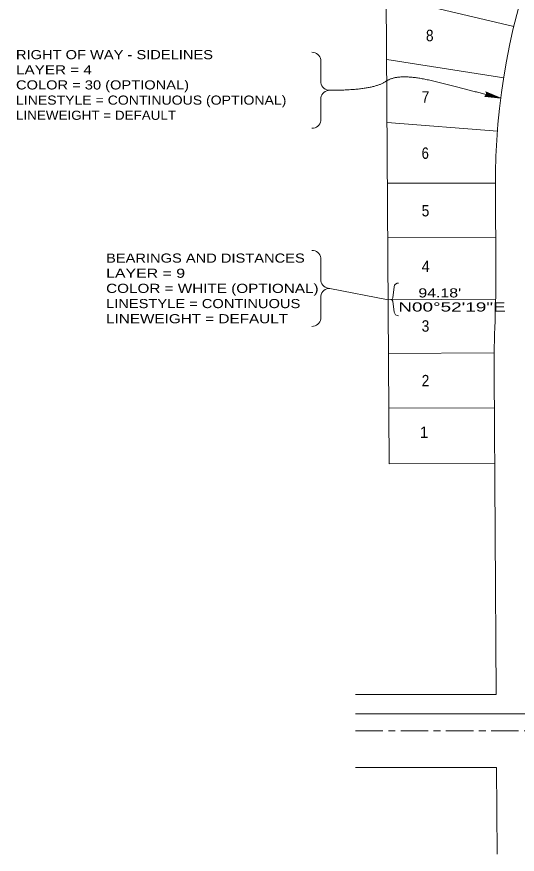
# Model space of a CAD drawing. Extents: x 6387474 to 6390971, y 1972046 to 1973920.
# Drawn here: x 6388753 to 6389192, y 1972046 to 1972779 of the extents above; entities that cross this region are included whole.
import ezdxf

# ---------------------------------------------------------------- set-up
doc = ezdxf.new("R2010")
doc.units = 0
doc.header["$LTSCALE"] = 4
doc.linetypes.add('LONG_DASH_SHORT_DASH', pattern=[9.9, 6, -1.2, 1.5, -1.2])
for name, color, linetype, lineweight in [('1', 7, 'Continuous', 13), ('2', 7, 'LONG_DASH_SHORT_DASH', 13), ('3', 7, 'Continuous', 13), ('4', 7, 'Continuous', 13), ('8', 7, 'Continuous', 13)]:
    doc.layers.add(name, color=color, linetype=linetype, lineweight=lineweight)
doc.layers.add('7', color=7, linetype='Continuous')

msp = doc.modelspace()

# ---------------------------------------------------------------- hatches: boundary and pattern name
at = {"layer": '8'}
for points in [[(6389177.432, 1972708.174), (6389163.863, 1972709.868), (6389163.361, 1972709.582)], [(6389177.432, 1972708.174), (6389164.286, 1972710.262), (6389163.863, 1972709.868)], [(6389177.432, 1972708.174), (6389164.608, 1972710.743), (6389164.286, 1972710.262)], [(6389164.318, 1972713.466), (6389164.629, 1972712.979), (6389177.432, 1972708.174)], [(6389164.81, 1972711.285), (6389164.608, 1972710.743), (6389177.432, 1972708.174)], [(6389164.629, 1972712.979), (6389164.821, 1972712.433), (6389177.432, 1972708.174)], [(6389164.882, 1972711.858), (6389164.81, 1972711.285), (6389177.432, 1972708.174)], [(6389164.821, 1972712.433), (6389164.882, 1972711.858), (6389177.432, 1972708.174)]]:
    msp.add_hatch(color=256, dxfattribs=at).paths.add_polyline_path(points)

# ---------------------------------------------------------------- linework, layer by layer
at = {"layer": '1'}
for p, q in [((6389072.576, 1973552.734), (6389079.624, 1972387.996)), ((6389079.624, 1972387.996), (6389172.122, 1972388.555))]:
    msp.add_line(p, q, dxfattribs=at)
at = {"layer": '2'}
msp.add_line((6389050.214, 1972153.984), (6389903.778, 1972153.984), dxfattribs=at)
at = {"layer": '3'}
for p, q in [((6389188.792, 1972770.788), (6389077.147, 1972797.257)), ((6389077.482, 1972741.929), (6389180.01, 1972725.798)), ((6389077.817, 1972686.64), (6389174.496, 1972679.126)), ((6389078.136, 1972633.771), (6389172.66, 1972633.627)), ((6389078.427, 1972585.832), (6389172.925, 1972586.404)), ((6389078.755, 1972531.513), (6389172.935, 1972532.083)), ((6389079.039, 1972484.534), (6389171.692, 1972485.095)), ((6389079.33, 1972436.475), (6389171.829, 1972437.035))]:
    msp.add_line(p, q, dxfattribs=at)
at = {"layer": '4'}
for p, q in [((6389172.666, 1972629.096), (6389173.104, 1972556.835)), ((6389171.645, 1972467.304), (6389173.348, 1972185.984)), ((6389050.214, 1972185.984), (6389173.348, 1972185.984)), ((6389050.213, 1972121.983), (6389173.735, 1972121.983)), ((6389173.735, 1972121.983), (6389174.195, 1972045.989))]:
    msp.add_line(p, q, dxfattribs=at)
for centre, radius, start, end in [((6389771.661, 1972632.72), 599, 137.65605, 180.34667), ((6388172.119, 1972551.261), 1001, 357.80051, 0.34648), ((6390196.627, 1972473.506), 1025, 177.8005, 180.34667)]:
    msp.add_arc(centre, radius, start, end, dxfattribs=at)
at = {"layer": '8'}
for p, q in [((6389019.82, 1972741.604), (6389019.82, 1972721.624)), ((6389019.82, 1972688.316), (6389019.82, 1972708.296)), ((6389019.82, 1972568.135), (6389019.82, 1972548.155)), ((6389078.755, 1972531.514), (6389027.708, 1972541.494)), ((6389084.019, 1972542.899), (6389082.813, 1972533.079)), ((6389019.82, 1972514.847), (6389019.82, 1972534.827)), ((6389082.812, 1972530.177), (6389084.022, 1972520.765)), ((6389050.214, 1972169.009), (6389919.45, 1972169.009))]:
    msp.add_line(p, q, dxfattribs=at)
for points in [[(6389075.095, 1972721.694), (6389075.585, 1972721.974), (6389076.055, 1972722.264), (6389076.507, 1972722.544), (6389076.94, 1972722.844), (6389077.371, 1972723.134), (6389077.816, 1972723.414), (6389078.276, 1972723.684), (6389078.75, 1972723.944), (6389079.239, 1972724.184), (6389079.743, 1972724.424), (6389080.262, 1972724.644), (6389080.795, 1972724.854), (6389081.342, 1972725.064), (6389081.905, 1972725.244), (6389082.482, 1972725.424), (6389083.073, 1972725.594), (6389083.679, 1972725.744), (6389084.3, 1972725.894), (6389084.936, 1972726.024), (6389085.586, 1972726.144), (6389086.251, 1972726.254), (6389086.93, 1972726.354), (6389087.624, 1972726.444), (6389088.333, 1972726.514), (6389089.056, 1972726.584), (6389089.794, 1972726.634), (6389090.547, 1972726.674), (6389091.314, 1972726.704), (6389092.096, 1972726.724), (6389092.893, 1972726.734), (6389093.704, 1972726.724), (6389094.53, 1972726.714), (6389095.371, 1972726.684), (6389096.226, 1972726.644), (6389097.095, 1972726.594), (6389097.98, 1972726.534), (6389098.879, 1972726.464), (6389099.793, 1972726.374), (6389100.721, 1972726.284), (6389101.664, 1972726.174), (6389102.622, 1972726.054), (6389103.594, 1972725.924), (6389104.581, 1972725.784), (6389105.582, 1972725.634), (6389106.598, 1972725.474), (6389107.629, 1972725.294), (6389108.675, 1972725.104), (6389109.735, 1972724.914), (6389110.81, 1972724.704), (6389111.899, 1972724.484), (6389113.003, 1972724.254)], [(6389113.003, 1972724.254), (6389114.122, 1972724.004), (6389115.255, 1972723.754), (6389116.403, 1972723.484), (6389117.566, 1972723.204), (6389118.743, 1972722.914), (6389119.935, 1972722.614), (6389121.132, 1972722.314), (6389122.324, 1972722.014), (6389123.513, 1972721.704), (6389124.697, 1972721.404), (6389125.877, 1972721.104), (6389127.052, 1972720.804), (6389128.223, 1972720.504), (6389129.39, 1972720.214), (6389130.553, 1972719.914), (6389131.711, 1972719.624), (6389132.865, 1972719.334), (6389134.014, 1972719.034), (6389135.16, 1972718.744), (6389136.3, 1972718.464), (6389137.437, 1972718.174), (6389138.569, 1972717.884), (6389139.697, 1972717.604), (6389140.821, 1972717.314), (6389141.94, 1972717.034), (6389143.056, 1972716.754), (6389144.166, 1972716.474), (6389145.273, 1972716.194), (6389146.375, 1972715.914), (6389147.473, 1972715.644), (6389148.566, 1972715.364), (6389149.655, 1972715.094), (6389150.74, 1972714.814), (6389151.821, 1972714.544), (6389152.897, 1972714.274), (6389153.969, 1972714.004), (6389155.036, 1972713.744), (6389156.1, 1972713.474), (6389157.159, 1972713.214), (6389158.213, 1972712.944), (6389159.264, 1972712.684), (6389160.31, 1972712.424), (6389161.351, 1972712.164), (6389162.389, 1972711.904), (6389163.422, 1972711.644), (6389164.451, 1972711.394), (6389165.475, 1972711.134), (6389166.495, 1972710.884), (6389167.511, 1972710.624), (6389168.523, 1972710.374), (6389169.53, 1972710.124), (6389170.533, 1972709.884), (6389171.531, 1972709.634), (6389172.525, 1972709.384), (6389173.515, 1972709.144), (6389174.501, 1972708.894), (6389175.482, 1972708.654), (6389176.459, 1972708.414), (6389177.432, 1972708.174)], [(6389027.708, 1972714.964), (6389029.133, 1972714.964), (6389030.539, 1972714.974), (6389031.926, 1972714.984), (6389033.294, 1972715.004), (6389034.643, 1972715.034), (6389035.972, 1972715.064), (6389037.283, 1972715.094), (6389038.574, 1972715.144), (6389039.847, 1972715.184), (6389041.1, 1972715.244), (6389042.334, 1972715.304), (6389043.549, 1972715.364), (6389044.745, 1972715.434), (6389045.922, 1972715.514), (6389047.08, 1972715.594), (6389048.219, 1972715.674), (6389049.339, 1972715.774), (6389050.439, 1972715.874), (6389051.521, 1972715.974), (6389052.583, 1972716.084), (6389053.627, 1972716.194), (6389054.651, 1972716.314), (6389055.656, 1972716.444), (6389056.642, 1972716.574), (6389057.609, 1972716.714), (6389058.557, 1972716.854), (6389059.486, 1972717.004), (6389060.396, 1972717.164), (6389061.287, 1972717.324), (6389062.158, 1972717.484), (6389063.011, 1972717.654), (6389063.845, 1972717.834), (6389064.659, 1972718.014), (6389065.454, 1972718.204), (6389066.231, 1972718.394), (6389066.988, 1972718.594), (6389067.726, 1972718.804), (6389068.445, 1972719.014), (6389069.145, 1972719.224), (6389069.826, 1972719.454), (6389070.487, 1972719.674), (6389071.13, 1972719.914), (6389071.754, 1972720.144), (6389072.358, 1972720.394), (6389072.944, 1972720.644), (6389073.51, 1972720.894), (6389074.057, 1972721.164), (6389074.585, 1972721.424), (6389075.095, 1972721.694)], [(6389163.361, 1972709.582), (6389177.432, 1972708.174), (6389164.318, 1972713.465)]]:
    msp.add_lwpolyline(points, dxfattribs=at)
for points in [[(6389177.432, 1972708.174), (6389163.863, 1972709.868), (6389163.361, 1972709.582)], [(6389177.432, 1972708.174), (6389164.286, 1972710.262), (6389163.863, 1972709.868)], [(6389177.432, 1972708.174), (6389164.608, 1972710.743), (6389164.286, 1972710.262)], [(6389164.318, 1972713.466), (6389164.629, 1972712.979), (6389177.432, 1972708.174)], [(6389164.81, 1972711.285), (6389164.608, 1972710.743), (6389177.432, 1972708.174)], [(6389164.629, 1972712.979), (6389164.821, 1972712.433), (6389177.432, 1972708.174)], [(6389164.882, 1972711.858), (6389164.81, 1972711.285), (6389177.432, 1972708.174)], [(6389164.821, 1972712.433), (6389164.882, 1972711.858), (6389177.432, 1972708.174)]]:
    msp.add_lwpolyline(points, close=True, dxfattribs=at)
for centre, radius, start, end in [((6389011.933, 1972740.267), 8, 9.61952, 90), ((6389027.708, 1972722.96), 8, 189.61952, 270), ((6389027.708, 1972706.96), 8, 90, 170.38048), ((6389162.383, 1972711.883), 2.5, 293.0279, 39.28811), ((6389011.933, 1972689.654), 8, 270, 350.38048), ((6389011.933, 1972566.797), 8, 9.61952, 90), ((6389027.708, 1972549.491), 8, 189.61952, 270), ((6389027.708, 1972533.491), 8, 90, 170.38048), ((6389087.667, 1972542.451), 3.676, 86.25389, 172.99909), ((6389081.168, 1972533.281), 1.657, 270, 352.99909), ((6389081.168, 1972529.966), 1.657, 7.3237, 90), ((6389087.667, 1972521.234), 3.676, 187.3237, 273.74611), ((6389011.933, 1972516.185), 8, 270, 350.38048)]:
    msp.add_arc(centre, radius, start, end, dxfattribs=at)

# ---------------------------------------------------------------- texts
at = {"layer": '7'}
for s, width, p in [('8', 0.9, (6389111.85, 1972757.938)), ('7', 0.9, (6389108.11, 1972704.12)), ('6', 0.85, (6389108.11, 1972654.919)), ('5', 0.9, (6389108.11, 1972604.546)), ('4', 0.95, (6389108.11, 1972555.786)), ('3', 0.9, (6389108.11, 1972503.571)), ('2', 0.9, (6389108.11, 1972455.708))]:
    msp.add_text(s, height=10, dxfattribs=dict(at, width=width)).set_placement(p)
msp.add_text('1', height=10, dxfattribs=at).set_placement((6389106.581, 1972410.543))
at = {"layer": '8'}
for s, width, p in [('RIGHT OF WAY - SIDELINES', 1.2, (6388752.7, 1972742.184)), ('LAYER = 4', 1.25, (6388752.722, 1972728.934)), ('COLOR = 30 (OPTIONAL)', 1.2, (6388752.736, 1972715.678)), ('LINESTYLE = CONTINUOUS (OPTIONAL)', 1.15, (6388752.736, 1972702.358)), ('LINEWEIGHT = DEFAULT', 1.1, (6388752.728, 1972689.1)), ('BEARINGS AND DISTANCES', 1.2, (6388831.638, 1972564.031)), ('LAYER = 9', 1.3, (6388831.66, 1972550.781)), ('COLOR = WHITE (OPTIONAL)', 1.25, (6388831.674, 1972537.525)), ("94.18'", 1.3, (6389105.212, 1972533.564)), ('LINESTYLE = CONTINUOUS', 1.2, (6388831.674, 1972524.205)), ('N00°52\'19"E', 1.55, (6389087.667, 1972521.235)), ('LINEWEIGHT = DEFAULT', 1.25, (6388831.666, 1972510.947))]:
    msp.add_text(s, height=8, dxfattribs=dict(at, width=width)).set_placement(p)

doc.saveas('drawing.dxf')
